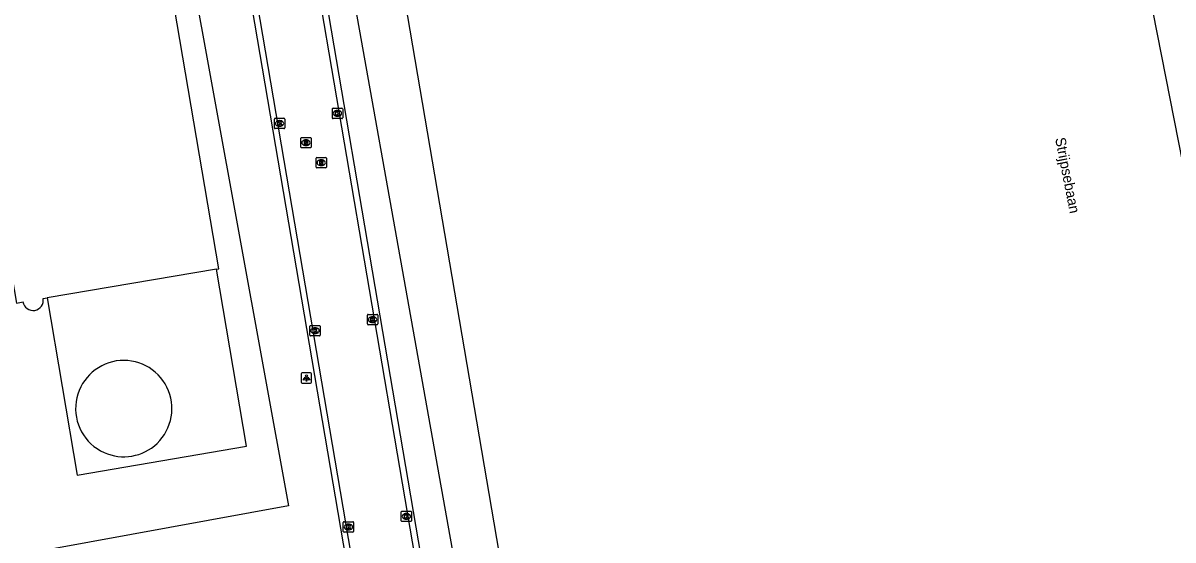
# Model space of a CAD drawing. Extents: x 154324 to 155743, y 382939 to 384183.
# Drawn here: x 154562 to 154673.2, y 383152.6 to 383202.5 of the extents above; entities that cross this region are included whole.
import ezdxf

# ---------------------------------------------------------------- set-up
doc = ezdxf.new("R2010")
doc.units = 0
for name, color, linetype in [('IMGEO_Bouwland', 7, 'Continuous'), ('IMGEO_Kolk', 7, 'Continuous'), ('IMGEO_Lichtpunt', 7, 'Continuous'), ('IMGEO_Openbare_ruimte_label', 7, 'Continuous'), ('IMGEO_Opslagtank', 7, 'Continuous'), ('IMGEO_Pand', 7, 'Continuous'), ('IMGEO_Pand_vergunning_verleend', 7, 'Continuous'), ('IMGEO_Rijbaan_lokaal_gesloten', 7, 'Continuous'), ('IMGEO_Rioolput', 7, 'Continuous')]:
    doc.layers.add(name, color=color, linetype=linetype)

msp = doc.modelspace()

# ---------------------------------------------------------------- linework, layer by layer
at = {"layer": 'IMGEO_Bouwland'}
msp.add_lwpolyline([(154564.35, 383175.93), (154567.26, 383158.81), (154583.64, 383161.62), (154580.73, 383178.71)], dxfattribs=at)
at = {"layer": 'IMGEO_Kolk'}
for p, q in [((154591.92, 383193.32), (154591.92, 383194.17)), ((154591.99, 383194.25), (154592.84, 383194.25)), ((154592.4, 383194.03), (154592.43, 383194.03)), ((154592.92, 383194.17), (154592.92, 383193.32)), ((154586.32, 383192.35), (154586.32, 383193.2)), ((154586.39, 383193.27), (154587.25, 383193.27)), ((154586.81, 383193.05), (154586.83, 383193.05)), ((154587.32, 383193.2), (154587.32, 383192.35)), ((154592.84, 383193.25), (154591.99, 383193.25)), ((154592.43, 383193.47), (154592.4, 383193.47)), ((154587.25, 383192.27), (154586.39, 383192.27)), ((154586.83, 383192.49), (154586.81, 383192.49)), ((154595.31, 383173.42), (154595.31, 383174.27)), ((154595.38, 383174.34), (154596.23, 383174.34)), ((154595.79, 383174.12), (154595.82, 383174.12)), ((154596.31, 383174.27), (154596.31, 383173.42)), ((154589.75, 383172.34), (154589.75, 383173.19)), ((154589.82, 383173.27), (154590.67, 383173.27)), ((154590.23, 383173.05), (154590.26, 383173.05)), ((154590.75, 383173.19), (154590.75, 383172.34)), ((154596.23, 383173.34), (154595.38, 383173.34)), ((154595.82, 383173.56), (154595.79, 383173.56)), ((154590.67, 383172.27), (154589.82, 383172.27)), ((154590.26, 383172.49), (154590.23, 383172.49)), ((154598.57, 383154.42), (154598.57, 383155.27)), ((154598.64, 383155.34), (154599.5, 383155.34)), ((154599.06, 383155.12), (154599.08, 383155.12)), ((154599.57, 383155.27), (154599.57, 383154.42)), ((154592.98, 383153.4), (154592.98, 383154.25)), ((154593.05, 383154.32), (154593.9, 383154.32)), ((154593.46, 383154.1), (154593.49, 383154.1)), ((154593.98, 383154.25), (154593.98, 383153.4)), ((154599.5, 383154.34), (154598.64, 383154.34)), ((154599.08, 383154.56), (154599.05, 383154.56)), ((154593.9, 383153.32), (154593.05, 383153.32)), ((154593.49, 383153.54), (154593.46, 383153.54))]:
    msp.add_line(p, q, dxfattribs=at)
for points in [[(154591.92, 383193.32), (154591.92, 383194.17)], [(154591.99, 383194.25), (154592.84, 383194.25)], [(154592.24, 383193.95), (154592.36, 383193.95), (154592.36, 383193.8), (154592.49, 383193.95), (154592.65, 383193.95), (154592.51, 383193.8), (154592.66, 383193.55), (154592.51, 383193.55), (154592.42, 383193.71), (154592.36, 383193.65), (154592.36, 383193.55), (154592.24, 383193.55), (154592.24, 383193.95)], [(154592.92, 383194.17), (154592.92, 383193.32)], [(154586.32, 383192.35), (154586.32, 383193.2)], [(154586.39, 383193.27), (154587.25, 383193.27)], [(154586.64, 383192.97), (154586.76, 383192.97), (154586.76, 383192.82), (154586.89, 383192.97), (154587.06, 383192.97), (154586.91, 383192.82), (154587.06, 383192.57), (154586.91, 383192.57), (154586.83, 383192.74), (154586.76, 383192.67), (154586.76, 383192.57), (154586.64, 383192.57), (154586.64, 383192.97)], [(154587.32, 383193.2), (154587.32, 383192.35)], [(154592.84, 383193.25), (154591.99, 383193.25)], [(154587.25, 383192.27), (154586.39, 383192.27)], [(154595.31, 383173.42), (154595.31, 383174.27)], [(154595.38, 383174.34), (154596.23, 383174.34)], [(154595.63, 383174.04), (154595.75, 383174.04), (154595.75, 383173.89), (154595.88, 383174.04), (154596.04, 383174.04), (154595.9, 383173.89), (154596.05, 383173.64), (154595.9, 383173.64), (154595.81, 383173.81), (154595.75, 383173.74), (154595.75, 383173.64), (154595.63, 383173.64), (154595.63, 383174.04)], [(154596.31, 383174.27), (154596.31, 383173.42)], [(154589.75, 383172.34), (154589.75, 383173.19)], [(154589.82, 383173.27), (154590.67, 383173.27)], [(154590.07, 383172.97), (154590.19, 383172.97), (154590.19, 383172.82), (154590.32, 383172.97), (154590.48, 383172.97), (154590.34, 383172.82), (154590.49, 383172.57), (154590.34, 383172.57), (154590.25, 383172.73), (154590.19, 383172.66), (154590.19, 383172.57), (154590.07, 383172.57), (154590.07, 383172.97)], [(154590.75, 383173.19), (154590.75, 383172.34)], [(154596.23, 383173.34), (154595.38, 383173.34)], [(154590.67, 383172.27), (154589.82, 383172.27)], [(154598.57, 383154.42), (154598.57, 383155.27)], [(154598.64, 383155.34), (154599.5, 383155.34)], [(154598.89, 383155.04), (154599.01, 383155.04), (154599.01, 383154.89), (154599.14, 383155.04), (154599.31, 383155.04), (154599.16, 383154.89), (154599.31, 383154.64), (154599.16, 383154.64), (154599.08, 383154.81), (154599.01, 383154.74), (154599.01, 383154.64), (154598.89, 383154.64), (154598.89, 383155.04)], [(154599.57, 383155.27), (154599.57, 383154.42)], [(154592.98, 383153.4), (154592.98, 383154.25)], [(154593.05, 383154.32), (154593.9, 383154.32)], [(154593.3, 383154.02), (154593.42, 383154.02), (154593.42, 383153.87), (154593.55, 383154.02), (154593.71, 383154.02), (154593.57, 383153.87), (154593.72, 383153.62), (154593.57, 383153.62), (154593.48, 383153.79), (154593.42, 383153.72), (154593.42, 383153.62), (154593.3, 383153.62), (154593.3, 383154.02)], [(154593.98, 383154.25), (154593.98, 383153.4)], [(154599.5, 383154.34), (154598.64, 383154.34)], [(154593.9, 383153.32), (154593.05, 383153.32)]]:
    msp.add_lwpolyline(points, dxfattribs=at)
for centre, start, end in [((154591.99, 383194.17), 91.552, 178.448), ((154591.99, 383194.17), 91.552, 178.448), ((154592.84, 383194.17), 1.552, 88.448), ((154592.84, 383194.17), 1.552, 88.448), ((154586.4, 383193.2), 91.552, 178.448), ((154586.4, 383193.2), 91.552, 178.448), ((154587.24, 383193.2), 1.552, 88.448), ((154587.24, 383193.2), 1.552, 88.448), ((154591.99, 383193.32), 181.552, 268.448), ((154591.99, 383193.32), 181.552, 268.448), ((154592.84, 383193.32), 271.552, 358.448), ((154592.84, 383193.32), 271.552, 358.448), ((154586.4, 383192.35), 181.552, 268.448), ((154586.4, 383192.35), 181.552, 268.448), ((154587.24, 383192.35), 271.552, 358.448), ((154587.24, 383192.35), 271.552, 358.448), ((154595.38, 383174.27), 91.552, 178.448), ((154595.38, 383174.27), 91.552, 178.448), ((154596.23, 383174.27), 1.552, 88.448), ((154596.23, 383174.27), 1.552, 88.448), ((154589.82, 383173.19), 91.552, 178.448), ((154589.82, 383173.19), 91.552, 178.448), ((154590.67, 383173.19), 1.552, 88.448), ((154590.67, 383173.19), 1.552, 88.448), ((154595.38, 383173.42), 181.552, 268.448), ((154595.38, 383173.42), 181.552, 268.448), ((154596.23, 383173.42), 271.552, 358.448), ((154596.23, 383173.42), 271.552, 358.448), ((154589.82, 383172.34), 181.552, 268.448), ((154589.82, 383172.34), 181.552, 268.448), ((154590.67, 383172.34), 271.552, 358.448), ((154590.67, 383172.34), 271.552, 358.448), ((154598.65, 383155.27), 91.552, 178.448), ((154598.65, 383155.27), 91.552, 178.448), ((154599.49, 383155.27), 1.552, 88.448), ((154599.49, 383155.27), 1.552, 88.448), ((154593.05, 383154.25), 91.552, 178.448), ((154593.05, 383154.25), 91.552, 178.448), ((154593.9, 383154.25), 1.552, 88.448), ((154593.9, 383154.25), 1.552, 88.448), ((154598.65, 383154.42), 181.552, 268.448), ((154598.65, 383154.42), 181.552, 268.448), ((154599.49, 383154.42), 271.552, 358.448), ((154599.49, 383154.42), 271.552, 358.448), ((154593.05, 383153.4), 181.552, 268.448), ((154593.05, 383153.4), 181.552, 268.448), ((154593.9, 383153.4), 271.552, 358.448), ((154593.9, 383153.4), 271.552, 358.448)]:
    msp.add_arc(centre, 0.0765, start, end, dxfattribs=at)
for centre, major_axis, ratio, start_param, end_param in [((154592.4, 383193.75), (-0.387, 0.002), 0.722429, 4.712389, 7.853982), ((154592.43, 383193.75), (-0.39, 0.002), 0.717154, 1.570796, 4.712389), ((154586.81, 383192.77), (-0.387, 0.002), 0.722429, 4.712389, 7.853982), ((154586.83, 383192.77), (-0.39, 0.002), 0.717154, 1.570796, 4.712389), ((154595.79, 383173.84), (-0.387, 0.002), 0.722429, 4.712389, 7.853982), ((154595.82, 383173.84), (-0.39, 0.002), 0.717154, 1.570796, 4.712389), ((154590.23, 383172.77), (-0.387, 0.002), 0.722429, 4.712389, 7.853982), ((154590.26, 383172.77), (-0.39, 0.002), 0.717154, 1.570796, 4.712389), ((154599.06, 383154.84), (-0.387, 0.002), 0.722429, 4.712389, 7.853982), ((154599.08, 383154.84), (-0.39, 0.002), 0.717154, 1.570796, 4.712389), ((154593.46, 383153.82), (-0.387, 0.002), 0.722429, 4.712389, 7.853982), ((154593.49, 383153.82), (-0.39, 0.002), 0.717154, 1.570796, 4.712389)]:
    msp.add_ellipse(centre, major_axis=major_axis, ratio=ratio, start_param=start_param, end_param=end_param, dxfattribs=at)
at = {"layer": 'IMGEO_Lichtpunt'}
for p, q in [((154588.92, 383168.61), (154588.92, 383167.81)), ((154588.92, 383168.61), (154588.92, 383167.81)), ((154589.82, 383168.71), (154589.01, 383168.71)), ((154589.82, 383168.71), (154589.01, 383168.71)), ((154589.92, 383167.81), (154589.92, 383168.61)), ((154589.92, 383167.81), (154589.92, 383168.61)), ((154589.01, 383167.71), (154589.82, 383167.71)), ((154589.01, 383167.71), (154589.82, 383167.71))]:
    msp.add_line(p, q, dxfattribs=at)
for points in [[(154589.29, 383168.28), (154589.33, 383168.25), (154589.14, 383167.99), (154589.11, 383168.01), (154589.29, 383168.28)], [(154589.39, 383168.23), (154589.44, 383168.23), (154589.44, 383167.91), (154589.39, 383167.91), (154589.39, 383168.23)], [(154589.5, 383168.25), (154589.54, 383168.28), (154589.73, 383168.01), (154589.69, 383167.99), (154589.5, 383168.25)]]:
    msp.add_lwpolyline(points, dxfattribs=at)
msp.add_circle((154589.42, 383168.41), 0.0994, dxfattribs=at)
for centre, start, end in [((154589.01, 383168.61), 90, 180), ((154589.01, 383168.61), 90, 180), ((154589.82, 383168.61), 0, 90), ((154589.82, 383168.61), 0, 90), ((154589.01, 383167.81), 180, 270), ((154589.01, 383167.81), 180, 270), ((154589.82, 383167.81), 270, 0), ((154589.82, 383167.81), 270, 360)]:
    msp.add_arc(centre, 0.0946, start, end, dxfattribs=at)
at = {"layer": 'IMGEO_Opslagtank'}
for centre, radius, start, end in [((154571.77, 383165.25), 4.65, 313.6643, 171.6858), ((154571.77, 383165.26), 4.66, 171.7012, 245.8309), ((154571.77, 383165.26), 4.66, 245.8538, 313.6585)]:
    msp.add_arc(centre, radius, start, end, dxfattribs=at)
at = {"layer": 'IMGEO_Pand'}
for points in [[(154580.73, 383178.71), (154580.95, 383178.75), (154564.29, 383276.58)], [(154640.12, 383035.63), (154639.96, 383035.6), (154623.69, 383130.92), (154616.87, 383129.75), (154616.83, 383129.75), (154616.71, 383130.48), (154612.74, 383129.8), (154612.11, 383133.49), (154611.26, 383133.35), (154609.37, 383144.42), (154609.22, 383144.4), (154590.4, 383254.85), (154588.66, 383265.07), (154600.5, 383267.08)], [(154422.8, 383252.54), (154442.14, 383154.08), (154469.46, 383158.8), (154468.8, 383162.6), (154560.93, 383178.26), (154561.39, 383175.43), (154562.03, 383175.54)], [(154580.73, 383178.71), (154564.35, 383175.93)], [(154563.98, 383175.87), (154564.35, 383175.93)]]:
    msp.add_lwpolyline(points, dxfattribs=at)
msp.add_arc((154563, 383175.71), 0.992, 189.843, 9.4331, dxfattribs=at)
at = {"layer": 'IMGEO_Pand_vergunning_verleend'}
for points in [[(154412.9, 383246.6), (154566.07, 383274.51), (154587.69, 383155.85), (154434.52, 383127.94), (154412.9, 383246.6)], [(154584.71, 383256.81), (154657.95, 383270.71), (154700.13, 383056.8), (154641.93, 383027.88), (154620.8, 383127.07), (154608.34, 383124.84), (154584.71, 383256.81)]]:
    msp.add_lwpolyline(points, dxfattribs=at)
at = {"layer": 'IMGEO_Rijbaan_lokaal_gesloten'}
for points in [[(154575.23, 383295.54), (154619.19, 383037.76), (154619.83, 383033.81)], [(154616, 383020.53), (154615, 383026.46), (154596.31, 383136.06), (154571.25, 383283.18)], [(154571.56, 383277.87), (154595.72, 383135.94), (154615.41, 383020.4)], [(154579.44, 383274.33), (154619.76, 383037.83), (154620.39, 383033.9)]]:
    msp.add_lwpolyline(points, dxfattribs=at)
at = {"layer": 'IMGEO_Rioolput'}
for p, q in [((154588.87, 383190.49), (154588.87, 383191.34)), ((154588.95, 383191.41), (154589.8, 383191.41)), ((154589.8, 383190.41), (154588.95, 383190.41)), ((154589.36, 383191.19), (154589.38, 383191.19)), ((154589.38, 383190.63), (154589.36, 383190.63)), ((154589.87, 383191.34), (154589.87, 383190.49)), ((154590.35, 383188.56), (154590.35, 383189.41)), ((154590.42, 383189.48), (154591.27, 383189.48)), ((154590.83, 383189.26), (154590.86, 383189.26)), ((154591.35, 383189.41), (154591.35, 383188.56)), ((154591.27, 383188.48), (154590.42, 383188.48)), ((154590.86, 383188.7), (154590.83, 383188.7))]:
    msp.add_line(p, q, dxfattribs=at)
for points in [[(154588.87, 383190.49), (154588.87, 383191.34)], [(154588.95, 383191.41), (154589.8, 383191.41)], [(154589.8, 383190.41), (154588.95, 383190.41)], [(154589.46, 383191.11), (154589.21, 383191.11), (154589.21, 383190.71)], [(154589.21, 383190.71), (154589.33, 383190.71), (154589.33, 383190.88), (154589.34, 383190.88)], [(154589.39, 383191.03), (154589.33, 383191.03), (154589.33, 383190.95)], [(154589.33, 383190.95), (154589.38, 383190.95)], [(154589.39, 383190.85), (154589.46, 383190.71), (154589.6, 383190.71), (154589.54, 383190.84)], [(154589.87, 383191.34), (154589.87, 383190.49)], [(154590.35, 383188.56), (154590.35, 383189.41)], [(154590.42, 383189.48), (154591.27, 383189.48)], [(154591.35, 383189.41), (154591.35, 383188.56)], [(154591.27, 383188.48), (154590.42, 383188.48)], [(154590.94, 383189.18), (154590.68, 383189.18), (154590.68, 383188.78)], [(154590.68, 383188.78), (154590.81, 383188.78), (154590.81, 383188.95), (154590.82, 383188.95)], [(154590.86, 383189.1), (154590.81, 383189.1), (154590.81, 383189.02)], [(154590.81, 383189.02), (154590.86, 383189.02)], [(154590.86, 383188.92), (154590.94, 383188.78), (154591.08, 383188.78), (154591.01, 383188.91)]]:
    msp.add_lwpolyline(points, dxfattribs=at)
for centre, radius, start, end in [((154588.95, 383191.34), 0.0765, 91.552, 178.448), ((154588.95, 383191.34), 0.0765, 91.552, 178.448), ((154588.95, 383190.49), 0.0765, 181.552, 268.448), ((154588.95, 383190.49), 0.0765, 181.552, 268.448), ((154589.34, 383190.82), 0.0533, 26.0293, 88.6989), ((154589.37, 383191.14), 0.19, 274.7715, 282.9687), ((154589.39, 383190.94), 0.0964, 77.0061, 93.1865), ((154589.41, 383190.99), 0.0378, 276.6634, 79.6772), ((154589.46, 383191), 0.109, 350.3612, 89.416), ((154589.46, 383191), 0.112, 277.5842, 350.9817), ((154589.44, 383190.79), 0.108, 29.5134, 73.7905), ((154589.8, 383191.34), 0.0765, 1.552, 88.448), ((154589.8, 383191.34), 0.0765, 1.552, 88.448), ((154589.8, 383190.49), 0.0765, 271.552, 358.448), ((154589.8, 383190.49), 0.0765, 271.552, 358.448), ((154590.42, 383189.41), 0.0765, 91.552, 178.448), ((154590.42, 383189.41), 0.0765, 91.552, 178.448), ((154591.27, 383189.41), 0.0765, 1.552, 88.448), ((154591.27, 383189.41), 0.0765, 1.552, 88.448), ((154590.42, 383188.56), 0.0765, 181.552, 268.448), ((154590.42, 383188.56), 0.0765, 181.552, 268.448), ((154590.82, 383188.89), 0.0533, 26.0293, 88.6989), ((154590.87, 383189.01), 0.0964, 77.0061, 93.1865), ((154590.84, 383189.21), 0.19, 274.7715, 282.9687), ((154590.88, 383189.06), 0.0378, 276.6634, 79.6772), ((154590.93, 383189.07), 0.109, 350.3612, 89.416), ((154590.93, 383189.07), 0.112, 277.5842, 350.9817), ((154590.92, 383188.86), 0.108, 29.5134, 73.7905), ((154591.27, 383188.56), 0.0765, 271.552, 358.448), ((154591.27, 383188.56), 0.0765, 271.552, 358.448)]:
    msp.add_arc(centre, radius, start, end, dxfattribs=at)
for centre, major_axis, ratio, start_param, end_param in [((154589.36, 383190.91), (-0.387, 0.002), 0.722429, 4.712389, 7.853982), ((154589.38, 383190.91), (-0.39, 0.002), 0.717154, 1.570796, 4.712389), ((154590.83, 383188.98), (-0.387, 0.002), 0.722429, 4.712389, 7.853982), ((154590.86, 383188.98), (-0.39, 0.002), 0.717154, 1.570796, 4.712389)]:
    msp.add_ellipse(centre, major_axis=major_axis, ratio=ratio, start_param=start_param, end_param=end_param, dxfattribs=at)

# ---------------------------------------------------------------- texts
at = {"layer": 'IMGEO_Openbare_ruimte_label'}
msp.add_text('Strijpsebaan', height=1, rotation=281.1301, dxfattribs=at).set_placement((154661.76, 383191.32))

doc.saveas('drawing.dxf')
